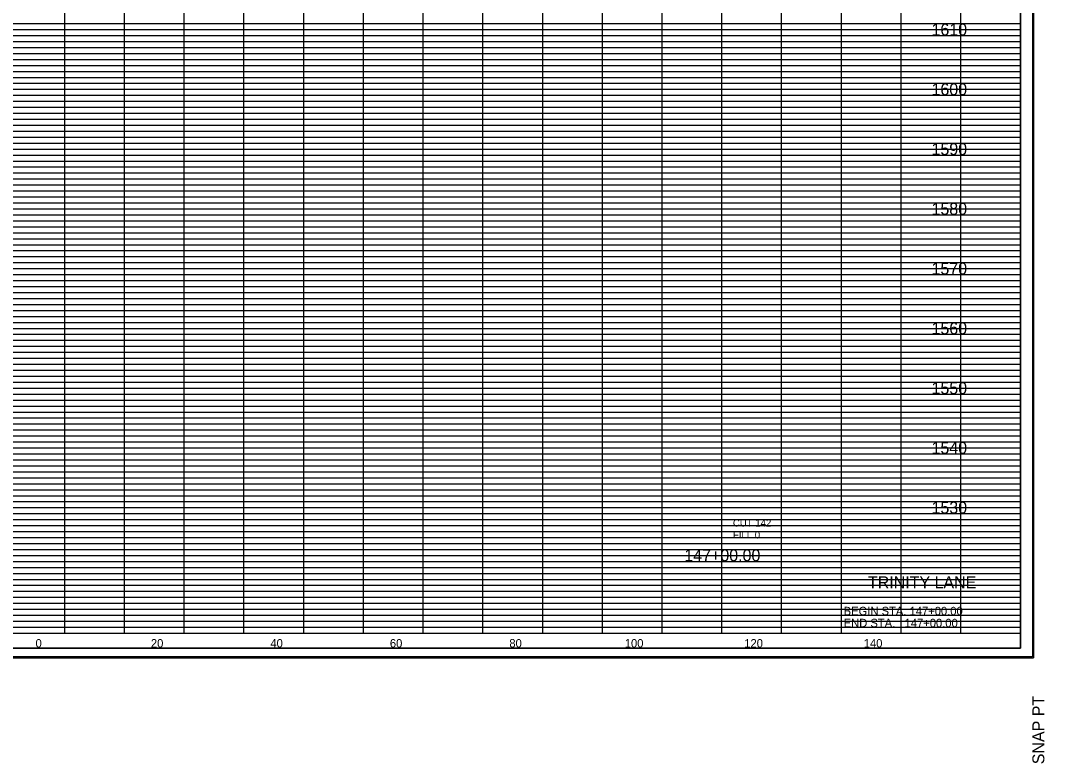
# Model space of a CAD drawing. Extents: x 980 to 1380, y 1248 to 3387.
# Drawn here: x 1152.6 to 1324, y 1788.2 to 1912.5 of the extents above; entities that cross this region are included whole.
import ezdxf

# ---------------------------------------------------------------- set-up
doc = ezdxf.new("R2010")
doc.units = 0
for name, color, linetype in [('DESIGN - SHEET - Corner Text', 7, 'Continuous'), ('DESIGN - SHEET - Light Grid', 7, 'Continuous'), ('DESIGN - SHEET - Linework', 7, 'Continuous'), ('DESIGN - SHEET - Plot Shape', 7, 'Continuous'), ('DESIGN - TYPICAL - Text', 7, 'Continuous')]:
    doc.layers.add(name, color=color, linetype=linetype)

# ---------------------------------------------------------------- blocks, each defined once
blk = doc.blocks.new('XSTSHT')
at = {"layer": 'DESIGN - SHEET - Light Grid'}
for p, q in [((8, 10.2), (16, 10.2)), ((16, 10.2), (24, 10.2)), ((24, 10.2), (32, 10.2)), ((8, 10.1), (16, 10.1)), ((16, 10.1), (24, 10.1)), ((24, 10.1), (32, 10.1)), ((8, 9.9), (16, 9.9)), ((8, 9.8), (16, 9.8)), ((16, 9.9), (24, 9.9)), ((16, 9.8), (24, 9.8)), ((24, 9.9), (32, 9.9)), ((24, 9.8), (32, 9.8)), ((8, 9.7), (16, 9.7)), ((8, 9.6), (16, 9.6)), ((16, 9.7), (24, 9.7)), ((16, 9.6), (24, 9.6)), ((24, 9.7), (32, 9.7)), ((24, 9.6), (32, 9.6)), ((8, 9.5), (16, 9.5)), ((16, 9.5), (24, 9.5)), ((24, 9.5), (32, 9.5)), ((8, 9.4), (16, 9.4)), ((8, 9.3), (16, 9.3)), ((16, 9.4), (24, 9.4)), ((16, 9.3), (24, 9.3)), ((24, 9.4), (32, 9.4)), ((24, 9.3), (32, 9.3)), ((8, 9.2), (16, 9.2)), ((8, 9.1), (16, 9.1)), ((16, 9.2), (24, 9.2)), ((16, 9.1), (24, 9.1)), ((24, 9.2), (32, 9.2)), ((24, 9.1), (32, 9.1)), ((8, 8.9), (16, 8.9)), ((8, 8.8), (16, 8.8)), ((16, 8.9), (24, 8.9)), ((16, 8.8), (24, 8.8)), ((24, 8.9), (32, 8.9)), ((24, 8.8), (32, 8.8)), ((8, 8.7), (16, 8.7)), ((8, 8.6), (16, 8.6)), ((16, 8.7), (24, 8.7)), ((16, 8.6), (24, 8.6)), ((24, 8.7), (32, 8.7)), ((24, 8.6), (32, 8.6)), ((8, 8.5), (16, 8.5)), ((8, 8.4), (16, 8.4)), ((16, 8.5), (24, 8.5)), ((16, 8.4), (24, 8.4)), ((24, 8.5), (32, 8.5)), ((24, 8.4), (32, 8.4)), ((8, 8.3), (16, 8.3)), ((16, 8.3), (24, 8.3)), ((24, 8.3), (32, 8.3)), ((8, 8.2), (16, 8.2)), ((8, 8.1), (16, 8.1)), ((16, 8.2), (24, 8.2)), ((16, 8.1), (24, 8.1)), ((24, 8.2), (32, 8.2)), ((24, 8.1), (32, 8.1)), ((8, 7.9), (16, 7.9)), ((16, 7.9), (24, 7.9)), ((24, 7.9), (32, 7.9)), ((8, 7.8), (16, 7.8)), ((16, 7.8), (24, 7.8)), ((24, 7.8), (32, 7.8)), ((8, 7.7), (16, 7.7)), ((8, 7.6), (16, 7.6)), ((16, 7.7), (24, 7.7)), ((16, 7.6), (24, 7.6)), ((24, 7.7), (32, 7.7)), ((24, 7.6), (32, 7.6)), ((8, 7.5), (16, 7.5)), ((8, 7.4), (16, 7.4)), ((16, 7.5), (24, 7.5)), ((16, 7.4), (24, 7.4)), ((24, 7.5), (32, 7.5)), ((24, 7.4), (32, 7.4)), ((8, 7.3), (16, 7.3)), ((8, 7.2), (16, 7.2)), ((16, 7.3), (24, 7.3)), ((16, 7.2), (24, 7.2)), ((24, 7.3), (32, 7.3)), ((24, 7.2), (32, 7.2)), ((8, 7.1), (16, 7.1)), ((16, 7.1), (24, 7.1)), ((24, 7.1), (32, 7.1)), ((8, 6.9), (16, 6.9)), ((16, 6.9), (24, 6.9)), ((24, 6.9), (32, 6.9)), ((8, 6.8), (16, 6.8)), ((8, 6.7), (16, 6.7)), ((16, 6.8), (24, 6.8)), ((16, 6.7), (24, 6.7)), ((24, 6.8), (32, 6.8)), ((24, 6.7), (32, 6.7)), ((8, 6.6), (16, 6.6)), ((16, 6.6), (24, 6.6)), ((24, 6.6), (32, 6.6)), ((8, 6.5), (16, 6.5)), ((8, 6.4), (16, 6.4)), ((16, 6.5), (24, 6.5)), ((16, 6.4), (24, 6.4)), ((24, 6.5), (32, 6.5)), ((24, 6.4), (32, 6.4)), ((8, 6.3), (16, 6.3)), ((8, 6.2), (16, 6.2)), ((16, 6.3), (24, 6.3)), ((16, 6.2), (24, 6.2)), ((24, 6.3), (32, 6.3)), ((24, 6.2), (32, 6.2)), ((8, 6.1), (16, 6.1)), ((16, 6.1), (24, 6.1)), ((24, 6.1), (32, 6.1)), ((8, 5.9), (16, 5.9)), ((16, 5.9), (24, 5.9)), ((24, 5.9), (32, 5.9)), ((8, 5.8), (16, 5.8)), ((8, 5.7), (16, 5.7)), ((16, 5.8), (24, 5.8)), ((16, 5.7), (24, 5.7)), ((24, 5.8), (32, 5.8)), ((24, 5.7), (32, 5.7)), ((8, 5.6), (16, 5.6)), ((8, 5.5), (16, 5.5)), ((16, 5.6), (24, 5.6)), ((16, 5.5), (24, 5.5)), ((24, 5.6), (32, 5.6)), ((24, 5.5), (32, 5.5)), ((8, 5.4), (16, 5.4)), ((16, 5.4), (24, 5.4)), ((24, 5.4), (32, 5.4)), ((8, 5.3), (16, 5.3)), ((8, 5.2), (16, 5.2)), ((16, 5.3), (24, 5.3)), ((16, 5.2), (24, 5.2)), ((24, 5.3), (32, 5.3)), ((24, 5.2), (32, 5.2)), ((8, 5.1), (16, 5.1)), ((16, 5.1), (24, 5.1)), ((24, 5.1), (32, 5.1)), ((8, 4.9), (16, 4.9)), ((8, 4.8), (16, 4.8)), ((16, 4.9), (24, 4.9)), ((16, 4.8), (24, 4.8)), ((24, 4.9), (32, 4.9)), ((24, 4.8), (32, 4.8)), ((8, 4.7), (16, 4.7)), ((16, 4.7), (24, 4.7)), ((24, 4.7), (32, 4.7)), ((8, 4.6), (16, 4.6)), ((8, 4.5), (16, 4.5)), ((16, 4.6), (24, 4.6)), ((16, 4.5), (24, 4.5)), ((24, 4.6), (32, 4.6)), ((24, 4.5), (32, 4.5)), ((8, 4.4), (16, 4.4)), ((8, 4.3), (16, 4.3)), ((16, 4.4), (24, 4.4)), ((16, 4.3), (24, 4.3)), ((24, 4.4), (32, 4.4)), ((24, 4.3), (32, 4.3)), ((8, 4.2), (16, 4.2)), ((16, 4.2), (24, 4.2)), ((24, 4.2), (32, 4.2)), ((8, 4.1), (16, 4.1)), ((16, 4.1), (24, 4.1)), ((24, 4.1), (32, 4.1)), ((8, 3.9), (16, 3.9)), ((8, 3.8), (16, 3.8)), ((16, 3.9), (24, 3.9)), ((16, 3.8), (24, 3.8)), ((24, 3.9), (32, 3.9)), ((24, 3.8), (32, 3.8)), ((8, 3.7), (16, 3.7)), ((8, 3.6), (16, 3.6)), ((16, 3.7), (24, 3.7)), ((16, 3.6), (24, 3.6)), ((24, 3.7), (32, 3.7)), ((24, 3.6), (32, 3.6)), ((8, 3.5), (16, 3.5)), ((16, 3.5), (24, 3.5)), ((24, 3.5), (32, 3.5)), ((8, 3.4), (16, 3.4)), ((8, 3.3), (16, 3.3)), ((16, 3.4), (24, 3.4)), ((16, 3.3), (24, 3.3)), ((24, 3.4), (32, 3.4)), ((24, 3.3), (32, 3.3)), ((8, 3.2), (16, 3.2)), ((8, 3.1), (16, 3.1)), ((16, 3.2), (24, 3.2)), ((16, 3.1), (24, 3.1)), ((24, 3.2), (32, 3.2)), ((24, 3.1), (32, 3.1)), ((8, 2.9), (16, 2.9)), ((8, 2.8), (16, 2.8)), ((16, 2.9), (24, 2.9)), ((16, 2.8), (24, 2.8)), ((24, 2.9), (32, 2.9)), ((24, 2.8), (32, 2.8)), ((8, 2.7), (16, 2.7)), ((8, 2.6), (16, 2.6)), ((16, 2.7), (24, 2.7)), ((16, 2.6), (24, 2.6)), ((24, 2.7), (32, 2.7)), ((24, 2.6), (32, 2.6)), ((8, 2.5), (16, 2.5)), ((8, 2.4), (16, 2.4)), ((16, 2.5), (24, 2.5)), ((16, 2.4), (24, 2.4)), ((24, 2.5), (32, 2.5)), ((24, 2.4), (32, 2.4)), ((8, 2.3), (16, 2.3)), ((16, 2.3), (24, 2.3)), ((24, 2.3), (32, 2.3)), ((8, 2.2), (16, 2.2)), ((8, 2.1), (16, 2.1)), ((16, 2.2), (24, 2.2)), ((16, 2.1), (24, 2.1)), ((24, 2.2), (32, 2.2)), ((24, 2.1), (32, 2.1)), ((8, 1.9), (16, 1.9)), ((16, 1.9), (24, 1.9)), ((24, 1.9), (32, 1.9)), ((8, 1.8), (16, 1.8)), ((16, 1.8), (24, 1.8)), ((24, 1.8), (32, 1.8)), ((8, 1.7), (16, 1.7)), ((8, 1.6), (16, 1.6)), ((16, 1.7), (24, 1.7)), ((16, 1.6), (24, 1.6)), ((24, 1.7), (32, 1.7)), ((24, 1.6), (32, 1.6)), ((8, 1.5), (16, 1.5)), ((8, 1.4), (16, 1.4)), ((16, 1.5), (24, 1.5)), ((16, 1.4), (24, 1.4)), ((24, 1.5), (32, 1.5)), ((24, 1.4), (32, 1.4)), ((8, 1.3), (16, 1.3)), ((8, 1.2), (16, 1.2)), ((16, 1.3), (24, 1.3)), ((16, 1.2), (24, 1.2)), ((24, 1.3), (32, 1.3)), ((24, 1.2), (32, 1.2)), ((8, 1.1), (16, 1.1)), ((16, 1.1), (24, 1.1)), ((24, 1.1), (32, 1.1)), ((8, 0.9), (16, 0.9)), ((16, 0.9), (24, 0.9)), ((24, 0.9), (32, 0.9)), ((8, 0.8), (16, 0.8)), ((8, 0.7), (16, 0.7)), ((16, 0.8), (24, 0.8)), ((16, 0.7), (24, 0.7)), ((24, 0.8), (32, 0.8)), ((24, 0.7), (32, 0.7)), ((8, 0.6), (16, 0.6)), ((16, 0.6), (24, 0.6)), ((24, 0.6), (32, 0.6)), ((8, 0.5), (16, 0.5)), ((8, 0.4), (16, 0.4)), ((16, 0.5), (24, 0.5)), ((16, 0.4), (24, 0.4)), ((24, 0.5), (32, 0.5)), ((24, 0.4), (32, 0.4)), ((8, 0.3), (16, 0.3)), ((8, 0.2), (16, 0.2)), ((16, 0.3), (24, 0.3)), ((16, 0.2), (24, 0.2)), ((24, 0.3), (32, 0.3)), ((24, 0.2), (32, 0.2)), ((8, 0.1), (16, 0.1)), ((16, 0.1), (24, 0.1)), ((24, 0.1), (32, 0.1))]:
    blk.add_line(p, q, dxfattribs=at)
at = {"layer": 'DESIGN - SHEET - Linework'}
for p, q in [((32.217, 21.414), (32.217, -0.414)), ((16, 0), (16, 21)), ((17, 0), (17, 21)), ((18, 0), (18, 21)), ((19, 0), (19, 21)), ((20, 0), (20, 21)), ((21, 0), (21, 21)), ((22, 0), (22, 21)), ((23, 0), (23, 21)), ((24, 0), (24, 21)), ((25, 0), (25, 21)), ((26, 0), (26, 21)), ((27, 0), (27, 21)), ((28, 0), (28, 20)), ((29, 0), (29, 20)), ((30, 0), (30, 20)), ((31, 0), (31, 20)), ((0, 10), (32, 10)), ((0, 9), (32, 9)), ((0, 8), (32, 8)), ((0, 7), (32, 7)), ((0, 6), (32, 6)), ((0, 5), (32, 5)), ((0, 4), (32, 4)), ((0, 3), (32, 3)), ((0, 2), (32, 2)), ((0, 1), (32, 1)), ((-1.823, -0.414), (32.217, -0.414))]:
    blk.add_line(p, q, dxfattribs=at)
blk.add_lwpolyline([(0, 21), (0, 0), (32, 0), (32, 21), (0, 21)], dxfattribs=at)
at = {"layer": 'DESIGN - SHEET - Plot Shape'}
for points in [[(-1.803, 21.394), (32.197, 21.394), (32.197, -0.394), (-1.803, -0.394)], [(-0.85, 21), (32, 21), (32, -0.25), (-0.85, -0.25)]]:
    blk.add_lwpolyline(points, close=True, dxfattribs=at)
at = {"layer": 'DESIGN - SHEET - Corner Text'}
blk.add_text('SNAP PT  ', height=0.2, rotation=90, dxfattribs=at).set_placement((32.397, -2.194))

msp = doc.modelspace()

# ---------------------------------------------------------------- linework, layer by layer
at = {"layer": 'DESIGN - SHEET - Plot Shape'}
msp.add_lwpolyline([(991.5, 1807.5), (1320, 1807.5), (1320, 2020), (991.5, 2020)], close=True, dxfattribs=at)

# ---------------------------------------------------------------- block references
at = {"layer": 'DESIGN - TYPICAL - Text', "xscale": 10, "yscale": 10}
msp.add_blockref('XSTSHT', (1000, 1810), dxfattribs=at)

# ---------------------------------------------------------------- texts
at = {"layer": 'DESIGN - SHEET - Corner Text'}
for s, height, p in [('TRINITY LANE', 2, (1294.45, 1817.5)), ('BEGIN STA. 147+00.00', 1.4, (1290.38, 1813)), ('END STA.   147+00.00', 1.4, (1290.38, 1811))]:
    msp.add_text(s, height=height, dxfattribs=at).set_placement(p)
at = {"layer": 'DESIGN - TYPICAL - Text'}
for s, height, p in [('     1610     ', 2, (1301.37, 1910)), ('     1600     ', 2, (1301.37, 1900)), ('     1590     ', 2, (1301.37, 1890)), ('     1580     ', 2, (1301.37, 1880)), ('     1570     ', 2, (1301.37, 1870)), ('     1560     ', 2, (1301.37, 1860)), ('     1550     ', 2, (1301.37, 1850)), ('     1540     ', 2, (1301.37, 1840)), ('     1530     ', 2, (1301.37, 1830)), ('CUT 142', 1.2, (1271.84, 1827.84)), ('FILL 0', 1.2, (1271.84, 1825.84)), ('     147+00.00     ', 2, (1260, 1822.02)), ('     0     ', 1.4, (1152.51, 1807.6)), ('     0     ', 1.4, (1152.51, 1807.6)), ('     20     ', 1.4, (1171.82, 1807.6)), ('     40     ', 1.4, (1191.82, 1807.6)), ('     60     ', 1.4, (1211.82, 1807.6)), ('     80     ', 1.4, (1231.82, 1807.6)), ('     100     ', 1.4, (1251.14, 1807.6)), ('     120     ', 1.4, (1271.14, 1807.6)), ('     140     ', 1.4, (1291.14, 1807.6))]:
    msp.add_text(s, height=height, dxfattribs=at).set_placement(p)

doc.saveas('drawing.dxf')
